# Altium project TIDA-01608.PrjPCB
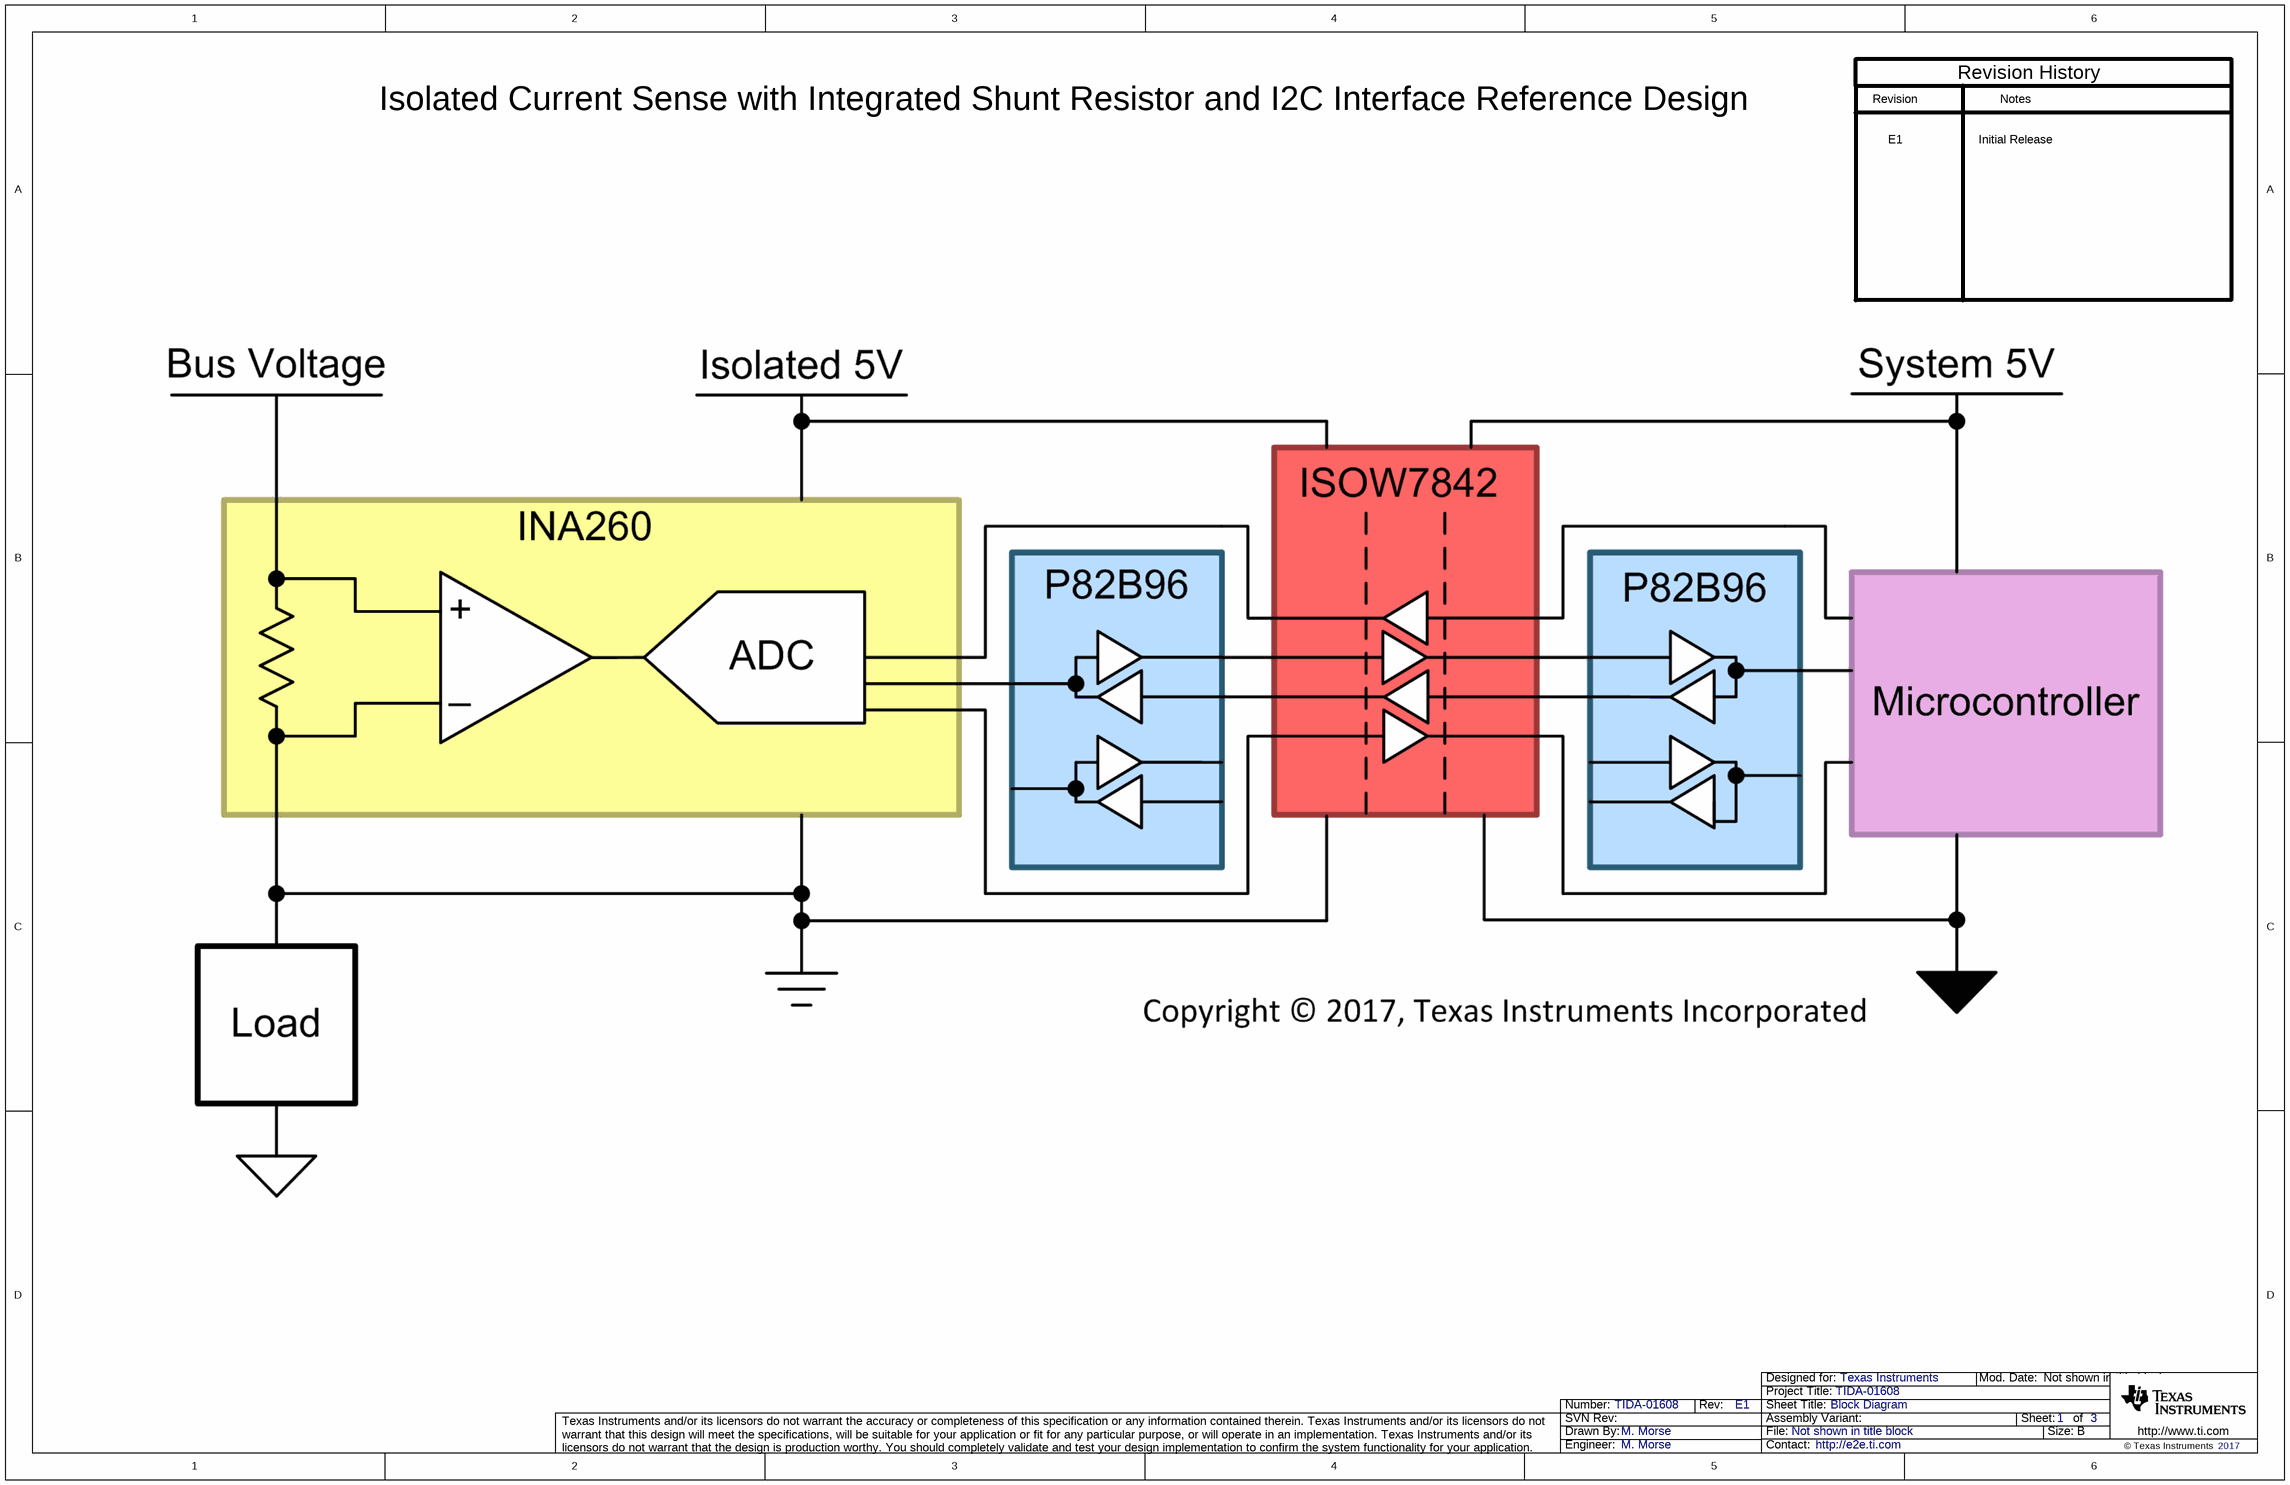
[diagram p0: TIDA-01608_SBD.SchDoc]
TechSupport: http://e2e.ti.com; SCH_Rev: E1; PRJ_Title: TIDA-01608; PRJ_Number: TIDA-01608; PRJ_Engineer: M. Morse; PRJ_Customer: Texas Instruments; PCB_Rev: E1; PCB_Layout: M. Morse; CopyrightYear: 2017
3 sheets, 67 parts. Net scope: global (net labels, ports and power ports of the same name join across sheets).
Board file: TIDA-01608_PCB.PcbDoc
Sheets:
  TIDA-01608_SBD.SchDoc
  TIDA-01608_SCH.SchDoc
  TIDA-01608_HW.SchDoc

## Sheet TIDA-01608_SBD.SchDoc: Block Diagram
size 431 x 279 mm; Date: Not shown in title block; ApprovedBy: Not shown in title block; CheckedBy: Not shown in title block; Author: Not shown in title block; CompanyName: Not shown in title block; DrawnBy: M. Morse; Engineer: Not shown in title block; Organization: Not shown in title block; Address1: Not shown in title block; Address2: Not shown in title block; Address3: Not shown in title block; Address4: Not shown in title block; DocumentNumber: 1; Revision: Use project parameter SCH_Rev; SheetNumber: 1; SheetTotal: 3; PageSetup: Record=PageOptions¦CenterHorizontal=True¦CenterVertical=True¦PrintScale=1.00¦XCorrection=1.00¦YCorrection=1.00¦PrintKind=0¦BorderSize=5000000¦LeftOffset=0¦BottomOffset=0¦Orientation=2¦PaperLength=1000¦PaperWidth=1000¦Scale=100¦PaperSource=15¦PrintQuality=600¦MediaType=1¦DitherType=10¦PaperKind=Letter¦PrintScaleMode=1

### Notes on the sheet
- Isolated Current Sense with Integrated Shunt Resistor and I2C Interface Reference Design
- Revision
- Notes
- Revision History
- E1
- Initial Release

## Sheet TIDA-01608_SCH.SchDoc: Main Schematic
size 431 x 279 mm; Date: Not shown in title block; ApprovedBy: Not shown in title block; CheckedBy: Not shown in title block; Author: Not shown in title block; CompanyName: Not shown in title block; DrawnBy: M. Morse; Engineer: Not shown in title block; Organization: Not shown in title block; Address1: Not shown in title block; Address2: Not shown in title block; Address3: Not shown in title block; Address4: Not shown in title block; DocumentNumber: 1; Revision: Use project parameter SCH_Rev; SheetNumber: 2; SheetTotal: 3; PageSetup: Record=PageOptions¦CenterHorizontal=True¦CenterVertical=True¦PrintScale=0.62¦XCorrection=1.00¦YCorrection=1.00¦PrintKind=0¦BorderSize=5000000¦LeftOffset=0¦BottomOffset=0¦Orientation=2¦PaperLength=1000¦PaperWidth=1000¦Scale=100¦PaperSource=15¦PrintQuality=600¦MediaType=1¦DitherType=10¦PaperKind=Letter¦PrintScaleMode=1
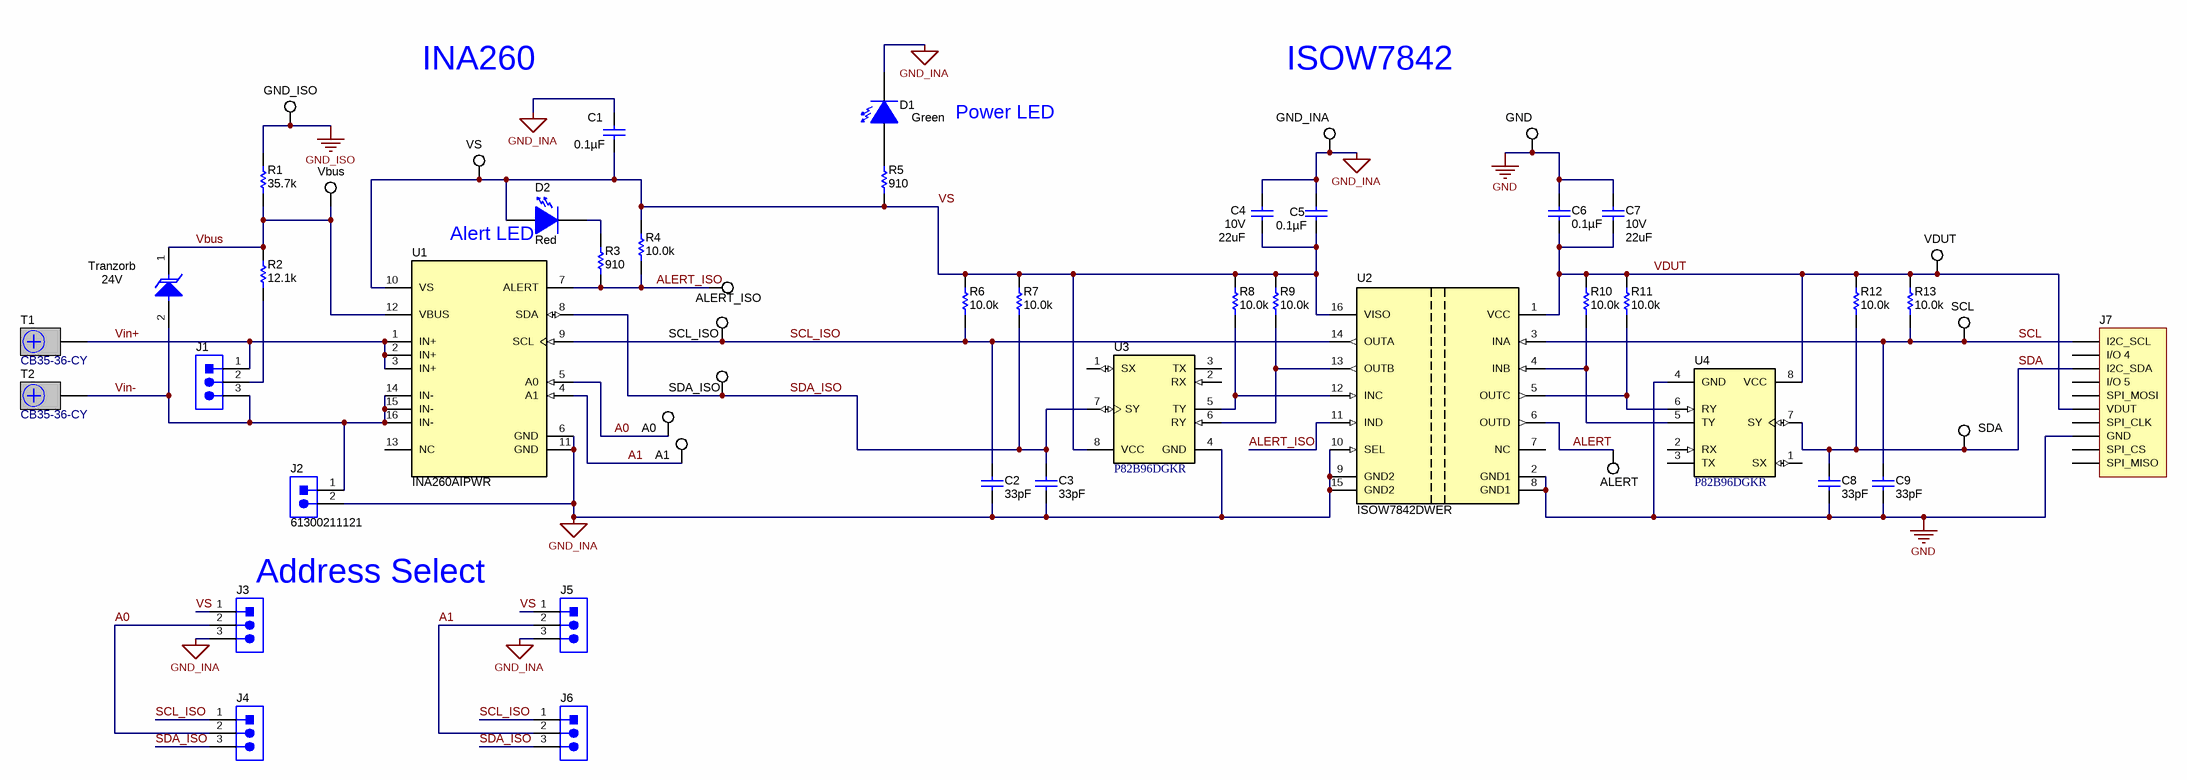
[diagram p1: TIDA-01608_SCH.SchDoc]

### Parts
C1  ValueDisplayed: 0.1µF  [0805_HV]  (hidden comment: 08055C104KAT2A)
C2  ValueDisplayed: 33pF  [0805_HV]  (hidden comment: 08051A330JAT2A)
C3  ValueDisplayed: 33pF  [0805_HV]  (hidden comment: 08051A330JAT2A)
C4  VDC_V: 10V  ValueDisplayed: 22uF  [0805_HV]  (hidden comment: GRM21BR61A226ME44L)
C5  ValueDisplayed: 0.1µF  [0805_HV]  (hidden comment: 08055C104KAT2A)
C6  ValueDisplayed: 0.1µF  [0805_HV]  (hidden comment: 08055C104KAT2A)
C7  VDC_V: 10V  ValueDisplayed: 22uF  [0805_HV]  (hidden comment: GRM21BR61A226ME44L)
C8  ValueDisplayed: 33pF  [0805_HV]  (hidden comment: 08051A330JAT2A)
C9  ValueDisplayed: 33pF  [0805_HV]  (hidden comment: 08051A330JAT2A)
D1  value Green  [LED_LTST-C190]  (hidden comment: LTST-C190GKT)
D2  value Red  [LED_LTST-C190_Red]  (hidden comment: LTST-C190CKT)
J1  61300311121  [WURTH_61300311121]  (value not drawn)
J2  61300211121  [WURTH_61300211121]
J3  61300311121  [WURTH_61300311121]  (value not drawn)
J4  61300311121  [WURTH_61300311121]  (value not drawn)
J5  61300311121  [WURTH_61300311121]  (value not drawn)
J6  61300311121  [WURTH_61300311121]  (value not drawn)
J7  851-43-010-20-001000  [851-43-010-20-001000]  (value not drawn)
R1  value 35.7k  [0805_HV]  (hidden comment: CRCW080535K7FKEA)
R2  value 12.1k  [0805_HV]  (hidden comment: CRCW080512K1FKEA)
R3  ValueDisplayed: 910  [0603]  (hidden comment: RC0603JR-07910RL)
R4  ValueDisplayed: 10.0k  [0603]  (hidden comment: ERJ-3EKF1002V)
R5  ValueDisplayed: 910  [0603]  (hidden comment: RC0603JR-07910RL)
R6  ValueDisplayed: 10.0k  [0805_HV]  (hidden comment: CRCW080510K0FKEA)
R7  ValueDisplayed: 10.0k  [0805_HV]  (hidden comment: CRCW080510K0FKEA)
R8  ValueDisplayed: 10.0k  [0805_HV]  (hidden comment: CRCW080510K0FKEA)
R9  ValueDisplayed: 10.0k  [0805_HV]  (hidden comment: CRCW080510K0FKEA)
R10  ValueDisplayed: 10.0k  [0805_HV]  (hidden comment: CRCW080510K0FKEA)
R11  ValueDisplayed: 10.0k  [0805_HV]  (hidden comment: CRCW080510K0FKEA)
R12  ValueDisplayed: 10.0k  [0805_HV]  (hidden comment: CRCW080510K0FKEA)
R13  ValueDisplayed: 10.0k  [0805_HV]  (hidden comment: CRCW080510K0FKEA)
T1  CB35-36-CY  [CB35-36-CY]
T2  CB35-36-CY  [CB35-36-CY]
TP2  GND_INA  [Testpoint_Keystone_Compact]
TP3  GND_ISO  [Testpoint_Keystone_Compact]
TP5  GND  [Testpoint_Keystone_Compact]
TP8  SCL_ISO  [Testpoint_Keystone_Compact]
TP9  SDA_ISO  [Testpoint_Keystone_Compact]
TP10  ALERT_ISO  [Testpoint_Keystone_Compact]
TP11  A0  [Testpoint_Keystone_Compact]
TP12  A1  [Testpoint_Keystone_Compact]
TP13  VDUT  [Testpoint_Keystone_Compact]
TP14  SCL  [Testpoint_Keystone_Compact]
TP15  SDA  [Testpoint_Keystone_Compact]
TP16  VS  [Testpoint_Keystone_Compact]
TP17  Vbus  [Testpoint_Keystone_Compact]
TP18  ALERT  [Testpoint_Keystone_Compact]
Tranzorb  value 24V  [SMB]  (hidden comment: SMBJ30A-13-F)
U1  INA260AIPWR  [PW0016A_N]
U2  ISOW7842DWER  [DWE0016A]
U3  P82B96DGKR  [DGK0008A_N]
U4  P82B96DGKR  [DGK0008A_N]

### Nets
GND: C6.2 C7.1 C8.2 C9.2 J7.8(GND) TP5.1 U2.2(GND1) U2.8(GND1) U4.4(GND)
GND_INA: C1.2 C2.2 C3.2 C4.1 C5.2 D1.2(K) J2.2 J3.3 J5.3 TP2.1 U1.6(GND) U1.11(GND) U2.9(GND2) U2.10(SEL) U2.15(GND2) U3.4(GND)
GND_ISO: R1.2 TP3.1
A0: J3.2 J4.2 TP11.1 U1.5(A0)
A1: J5.2 J6.2 TP12.1 U1.4(A1)
ALERT: TP18.1 U2.6(OUTD)
ALERT_ISO: R3.2 R4.2 TP10.1 U1.7(ALERT) U2.11(IND)
SCL: C9.1 J7.1(I2C_SCL) R13.1 TP14.1 U2.3(INA)
SCL_ISO: C2.1 J4.1 J6.1 R6.1 TP8.1 U1.9(SCL) U2.14(OUTA)
SDA: C8.1 J7.3(I2C_SDA) R12.1 TP15.1 U4.7(SY)
SDA_ISO: C3.1 J4.3 J6.3 R7.1 TP9.1 U1.8(SDA) U3.7(SY)
Vbus: R1.1 R2.2 TP17.1 Tranzorb.1(K) U1.12(VBUS)
VDUT: C6.1 C7.2 J7.6(VDUT) R10.2 R11.2 R12.2 R13.2 TP13.1 U2.1(VCC) U4.8(VCC)
Vin+: J1.1 T1.1 U1.1(IN+) U1.2(IN+) U1.3(IN+)
Vin-: J1.3 J2.1 T2.1 Tranzorb.2(A) U1.14(IN-) U1.15(IN-) U1.16(IN-)
VS: C1.1 C4.2 C5.1 D2.1(A) J3.1 J5.1 R4.1 R5.2 R6.2 R7.2 R8.2 R9.2 TP16.1 U1.10(VS) U2.16(VISO) U3.8(VCC)
NetD1_1: D1.1(A) R5.1
NetD2_2: D2.2(K) R3.1
NetJ1_2: J1.2 R2.1
NetR8_1: R8.1 U2.12(INC) U3.5(TY)
NetR9_1: R9.1 U2.13(OUTB) U3.6(RY)
NetR10_1: R10.1 U2.4(INB) U4.5(TY)
NetR11_1: R11.1 U2.5(OUTC) U4.6(RY)

Not connected (* = marked no-connect by the designer): J7 2(I/O_4) 4(I/O_5) 5(SPI_MOSI) 7(SPI_CLK) 9(SPI_CS) 10(SPI_MISO); U1 13(NC); U2 7(NC); U3 1(SX) 2(RX) 3(TX); U4 1(SX) 2(RX) 3(TX)

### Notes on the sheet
- INA260
- Power LED
- ISOW7842
- (near D2) Alert LED
- (near J3) Address Select

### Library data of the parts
C1 C5 C6 = 08055C104KAT2A: CAP, CERM, 0.1uF, 50V, +/-10%, X7R, 0805; Manufacturer: AVX; Polarized: N; CompType: Capacitor; U/M: EA; Cap_F: 0.0000001; Tolerance_%: 10; ESR_Ohm: 0.024; Value1: 0.024 ohm; VDC_V: 50; TaMin_C: -55; TaMax_C: 125; Cap_Case: 0805
C2 C3 C8 C9 = 08051A330JAT2A: CAP, CERM, 33 pF, 100 V,+/- 5%, C0G/NP0, 0805; Manufacturer: AVX; Polarized: N; CompType: Capacitor; Value: 33pF; U/M: EA; Cap_F: 0.000000000033; Tolerance_%: 5; ESR_ohm: 0.708; Value1: 0.708 ohm; VDC_V: 100; Value2: 100V; TaMin_C: -55; TaMax_C: 125; Cap_Case: 0805; SizeArea_mm2: 2.5; SizeAreaWB_mm2: 6.75; SizeX_mm: 2; SizeY_mm: 1.25; SizeZ_mm: 1.45; AEC Category: Q200; Green_Lifecycle: Not Set; Green_REACh: Incomplete
C4 C7 = CMP-0008286-2: CAP, CERM, 22 uF, 10 V, +/- 20%, X5R, 0805; Manufacturer: MuRata; TaMin_C: -55°C; Polarized: N; SizeAreaWB_mm2: 6.75; Value1: Unknown; U/M: EA; Value: 22uF; TaMax_C: 85°C; SizeZ_mm: 1.45; SizeX_mm: 2; SizeY_mm: 1.25; Cap_Case: 0805; SizeArea_mm2: 2.5; Cap_F: 22µF; AEC Category: Q200
D1 = LTST-C190GKT: LED, Green, SMD; Manufacturer: Lite-On; Vf_V: 2.1; Value2: 2.1V; Io_A: 0.02; Power_TotalModule: 0.1; Value1: 0.1W; U/M: EA
D2 = LTST-C190CKT: LED, Red, SMD; Manufacturer: Lite-On; Vf_V: 2; Value2: 2V; Io_A: 0.02; Tjmax_C: 85; Power_TotalModule: 0.0625; Value1: 0.0625W; U/M: EA
J1 J3-J6 = CMP-0054796-1: Header, 2.54 mm, 3x1, Gold, TH; Manufacturer: Wurth Elektronik; CNHeader: TRUE; Green_Lifecycle: Active; Green_REACh: Passed; CT: FALSE
J2 = 61300211121: Header, 2.54 mm, 2x1, Gold, TH; Manufacturer: Wurth Elektronik; SymbolCreator: a0412235; Green_Lifecycle: Active; Green_REACh: Passed
J7 = SM-USB-DIG-CONN: 10-Pin 50-mil Connector of SM-USB-DIG; Manufacturer: Mill-Max Manufacturing Corp.; SymbolCreator: Use LDAP id; CompType: Conn; U/M: EA, IN, or GM
R1 = CRCW080535K7FKEA: RES, 35.7k ohm, 1%, 0.125W, 0805; Manufacturer: Vishay-Dale; CompType: Resistor; Res_ohm: 35700; Value_Code: 35k7; Tolerance_%: 1; Power_W: 0.125; VDC_V: 150; TempCo: 100 ppm/C; EIA_Code: E96; U/M: EA
R2 = CRCW080512K1FKEA: RES, 12.1k ohm, 1%, 0.125W, 0805; Manufacturer: Vishay-Dale; CompType: Resistor; Res_ohm: 12100; Value_Code: 12k1; Tolerance_%: 1; Power_W: 0.125; VDC_V: 150; TempCo: 100 ppm/C; EIA_Code: E96; U/M: EA
R3 R5 = CMP-0025943-2: RES, 910, 5%, 0.1 W, 0603; Manufacturer: Yageo America; Power_W: 100mW; TempCo: 100 ppm/C; Value_Code: 910R; U/M: EA; Value: 910; EIA_Code: E24; SizeX_mm: 1.6; SizeY_mm: 0.8; SizeZ_mm: 1; Value2: 0.1W; SizeArea_mm2: 1.28; VDC_V: 50V; AEC Category: Q200
R4 = CMP-0022684-2: RES, 10.0 k, 1%, 0.1 W, 0603; Manufacturer: Panasonic; Power_W: 100mW; TempCo: 100 ppm/C; Value_Code: 10k0; U/M: EA; Value: 10.0k; EIA_Code: E96; Res_ohm: 10k; SizeX_mm: 1.6; SizeY_mm: 0.8; SizeZ_mm: 1; Value2: 0.1W; SizeArea_mm2: 1.28; VDC_V: 75V; AEC Category: Q200
R6-R13 = CRCW080510K0FKEA: RES, 10.0 k, 1%, 0.125 W, 0805; Manufacturer: Vishay-Dale; CompType: Resistor; Value: 10.0k; Res_ohm: 10000; Value_Code: 10k0; Tolerance_%: 1; Power_W: 0.125; Value2: 0.125W; VDC_V: 150; TempCo: 100 ppm/C; SizeArea_mm2: 2.5; SizeX_mm: 2; SizeY_mm: 1.25; SizeZ_mm: 1.45; EIA_Code: E96; U/M: EA; AEC Category: Q200; Green_Lifecycle: Active; Green_REACh: Passed
T1 T2 = CB35-36-CY: Terminal 50A Lug; Manufacturer: Panduit; SymbolCreator: crossc; CompType: Screw Terminal; ContactFinish: Copper; Voltage_V: 600; Cert_CULUS: Y; Green_Lifecycle: Not Set; Green_REACh: Incomplete
TP2 TP3 TP5 TP8-TP18 = 5016: Test Point, Compact, SMT; Manufacturer: Keystone; CompType: Test Point Loop; U/M: EA
Tranzorb = SMBJ24A-13-F: Diode, TVS, Uni, 24V, 600W, SMB; Manufacturer: Diodes Inc.; U/M: EA; Power_W: 5; Vr_V: 24; Value1: 5W
U1 = INA260AIPWR: High/Low-Side Digital Current/Power Monitor with Integrated 2mΩ Shunt Resistor, PW0016A (TSSOP-16); Manufacturer: Texas Instruments; SymbolCreator: Altium; SizeArea_mm2: 32; SizeAreaWB_mm2: 58.8; SizeX_mm: 6.4; SizeY_mm: 5; SizeZ_mm: 1.2; CompType: IC; U/M: EA
U2 = ISOW7842DWER: High-Performance, 5000-VRMS Reinforced Quad-Channel Digital Isolators With Integrated High-Efficiency, Low-Emissions DC-DC Converter, DWE0016A (SOIC-16); Manufacturer: Texas Instruments; SymbolCreator: Altium; SizeArea_mm2: 106.09; SizeAreaWB_mm2: 151.29; SizeX_mm: 10.3; SizeZ_mm: 2.65; CompType: IC; U/M: EA
U3 U4 = P82B96DGKR: Dual Bidirectional Bus Buffer, 2 Channel Width, 2.0 to 15.0 V, -40 to 85 degC, 8-pin MSOP (DGK), Green (RoHS & no Sb/Br); Manufacturer: Texas Instruments; Alternate PartNumber: Equivalent; SubFamily: I2C Hub, Buffer, Repeater; No. of Outputs: 2; VCC(Max)(V): 15; Max Frequency(kHz): 400; 5V Tolerant I/O: Yes

## Sheet TIDA-01608_HW.SchDoc: Hardware and Logos
size 431 x 279 mm; Date: Not shown in title block; ApprovedBy: Not shown in title block; CheckedBy: Not shown in title block; Author: Not shown in title block; CompanyName: Not shown in title block; DrawnBy: M. Morse; Engineer: Not shown in title block; Organization: Not shown in title block; Address1: Not shown in title block; Address2: Not shown in title block; Address3: Not shown in title block; Address4: Not shown in title block; DocumentNumber: 1; Revision: Use project parameter SCH_Rev; SheetNumber: 3; SheetTotal: 3; PageSetup: Record=PageOptions¦CenterHorizontal=True¦CenterVertical=True¦PrintScale=1.00¦XCorrection=1.00¦YCorrection=1.00¦PrintKind=0¦BorderSize=5000000¦LeftOffset=0¦BottomOffset=0¦Orientation=2¦PaperLength=1000¦PaperWidth=1000¦Scale=100¦PaperSource=15¦PrintQuality=600¦MediaType=1¦DitherType=10¦PaperKind=Letter¦PrintScaleMode=1
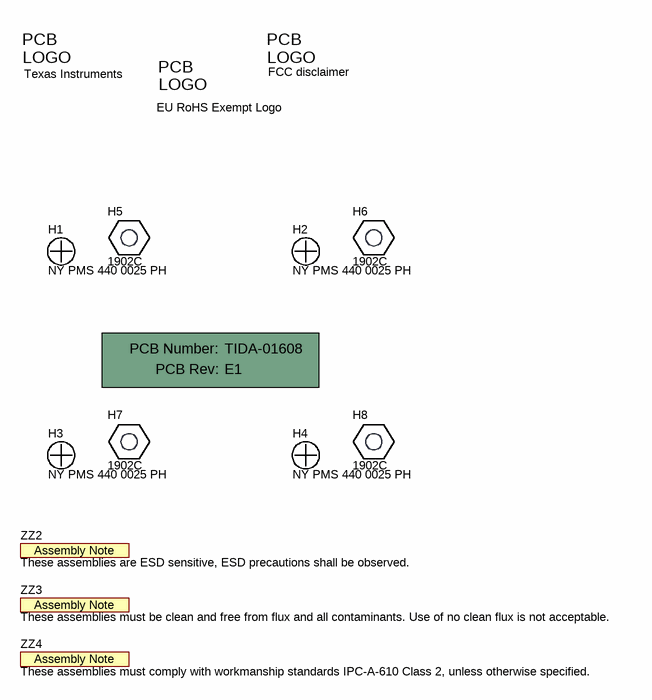
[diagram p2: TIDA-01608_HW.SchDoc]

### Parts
!PCB  Printed Circuit Board  (value not drawn)  (mechanical)
H1  NY PMS 440 0025 PH  [NY PMS 440 0025 PH]
H2  NY PMS 440 0025 PH  [NY PMS 440 0025 PH]
H3  NY PMS 440 0025 PH  [NY PMS 440 0025 PH]
H4  NY PMS 440 0025 PH  [NY PMS 440 0025 PH]
H5  1902C  [Keystone_1902C]
H6  1902C  [Keystone_1902C]
H7  1902C  [Keystone_1902C]
H8  1902C  [Keystone_1902C]
Logo1  Texas Instruments  [TI_Symbol_Overlay_Small]  (no BOM)
Logo2  EU RoHS Exempt Logo  [EURoHS_Exempt_60mil]  (no BOM)
Logo3  FCC disclaimer  [FCC_disclaimer_stacked]  (no BOM)
ZZ2  These assemblies are ESD sensitive, ESD precautions shall be observed.  [AssemblyNote]  (no BOM)
ZZ3  These assemblies must be clean and free from flux and all contaminants. Use of no clean flux is not acceptable.  [AssemblyNote]  (no BOM)
ZZ4  These assemblies must comply with workmanship standards IPC-A-610 Class 2, unless otherwise specified.  [AssemblyNote]  (no BOM)

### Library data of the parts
!PCB = PCB: Manufacturer: Any; PartNumber: TIDA-01608; SymbolCreator: a0412235
H1-H4 = NY PMS 440 0025 PH: Machine Screw, Round, #4-40 x 1/4, Nylon, Philips panhead; Manufacturer: B&F Fastener Supply; CompType: Hardware; SymbolCreator: codlsc; U/M: EA
H5-H8 = 1902C: Standoff, Hex, 0.5"L #4-40 Nylon; Manufacturer: Keystone; CompType: Hardware
Logo1 = TI_Logo: Texas Instrument Corporate Signature; SymbolCreator: codlsc
Logo2 = EURoHS_Exempt: SymbolCreator: a0412235
Logo3 = FCC_disclaimer: SymbolCreator: codlsc
ZZ2 = CMP-0077236-1
ZZ3 = CMP-0077237-1
ZZ4 = CMP-0077238-1

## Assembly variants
001: all parts fitted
